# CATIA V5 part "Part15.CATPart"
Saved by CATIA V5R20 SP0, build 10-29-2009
Part number: 3IMAN5X2
Revision: ANY
Definition: UNKNOWN
Nomenclature: 3IMAN5X2
Source: Unknown
Bounding box of the stored display mesh (mm): x -2.5 to 2.5, y 0 to 2, z -2.5 to 2.5
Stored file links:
  C:\Users\Utente\Desktop\IO LAVORO\3D X SITO CF\CUMSA\3D files CG\CG 754049\Part15.CATPart
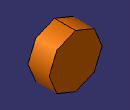
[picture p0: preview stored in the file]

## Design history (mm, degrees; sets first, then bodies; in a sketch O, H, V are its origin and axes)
Body1 "Saliente-Extruir1" (main body)
  Solid1: solid without history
